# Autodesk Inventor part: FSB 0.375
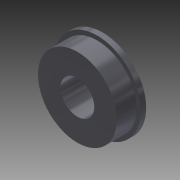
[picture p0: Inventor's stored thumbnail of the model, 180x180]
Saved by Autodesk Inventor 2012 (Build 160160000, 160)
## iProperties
Created: 2011-05
Part Number: FSB 0.375
Document SubType Name: Modeling
Designer: Alex
Density: 7.84 g/cm^3
Material: Steel, High Strength Low Alloy
Mass: 18.6958 g
Surface Area: 15.2778 cm^2
Volume: 2.38467 cm^3
Author: Alex
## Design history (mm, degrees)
sketch "Sketch1"
  geometry: C1 r 12.294 at (0, 0); 1 further point
  constraints: 1 centre point, 1 coincident
  dimensions: "d0" = 24.5872 diameter of C1
extrude "Extrusion1" new body sketch "Sketch1" distance "d3" = 1.524; taper "d4" = 0 deg
sketch "Sketch2"
  geometry: C1 r 12.294 at (0, 0) reference; C2 r 11.113 at (0, 0)
  constraints: 1 centre point, 1 coincident
  dimensions: "d5" = 22.225 diameter of C2
extrude "Extrusion2" join sketch "Sketch2" distance "d6" = 5.588; taper "d7" = 0 deg
sketch "Sketch3"
  geometry: C1 r 11.112 at (0, 0) reference; 1 further point
  constraints: 1 coincident
hole "Hole1" sketch "Sketch3" at (0, 0) diameter "d8" = 9.525; stored, may be unused: countersink angle "d12" = 82 deg, drill point angle "d14" = 118 deg; dims "d9" = 19.05, "d10" = 9.525, "d11" = 6.35, "d13" = 25.4
body "Solid1"
